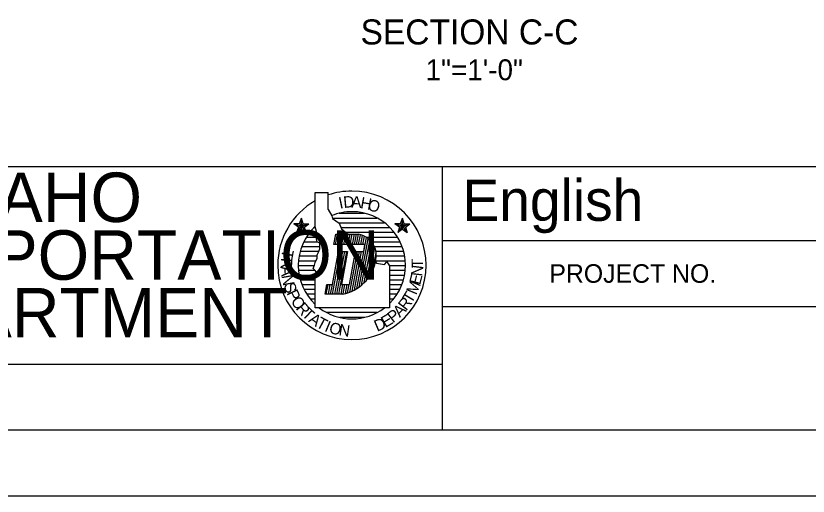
# Model space of a CAD drawing. Extents: x 0 to 34, y 0 to 23.5.
# Drawn here: x 16.02 to 22.02, y 0 to 3.64 of the extents above; entities that cross this region are included whole.
import ezdxf

# ---------------------------------------------------------------- set-up
doc = ezdxf.new("R2010")
doc.units = 0
for name, color, linetype in [('BORDER_ANNO_Cutsheet', 7, 'Continuous'), ('BRDG_ANNO_Anno-Sheet', 7, 'Continuous'), ('BRDG_ANNO_General-Notes', 7, 'Continuous')]:
    doc.layers.add(name, color=color, linetype=linetype)

msp = doc.modelspace()

# ---------------------------------------------------------------- linework, layer by layer
at = {"layer": 'BORDER_ANNO_Cutsheet'}
msp.add_lwpolyline([(0, 22), (34, 22), (34, 0), (0, 0)], close=True, dxfattribs=at)
at = {"layer": 'BRDG_ANNO_Anno-Sheet'}
for p, q in [((1.5, 2.5), (19.25, 2.5)), ((19.25, 0.5), (19.25, 2.5)), ((19.25, 2.5), (33.5, 2.5)), ((18.2844, 2.0425), (18.2844, 2.3031)), ((18.2844, 2.3031), (18.3831, 2.3031)), ((18.3831, 2.1731), (18.3831, 2.3031)), ((18.3831, 2.1731), (18.4094, 2.1262)), ((18.1656, 2.0656), (18.1794, 2.1069)), ((18.1794, 2.0237), (18.1794, 2.1069)), ((18.1931, 2.0656), (18.1794, 2.1069)), ((18.4094, 2.1262), (18.4144, 2.105)), ((18.4144, 2.105), (18.4662, 2.0688)), ((18.4169, 2.1081), (18.7506, 2.1081)), ((18.465, 2.1444), (18.6581, 2.1444)), ((18.9319, 2.0656), (18.9456, 2.1069)), ((18.9456, 2.0237), (18.9456, 2.1069)), ((18.9594, 2.0656), (18.9456, 2.1069)), ((18.2012, 2.04), (18.1225, 2.0656)), ((18.1656, 2.0656), (18.1225, 2.0656)), ((18.1575, 2.04), (18.1225, 2.0656)), ((18.1931, 2.0656), (18.1438, 1.9981)), ((18.1575, 2.04), (18.2369, 2.0656)), ((18.1656, 2.0656), (18.215, 1.9981)), ((18.1931, 2.0656), (18.2369, 2.0656)), ((18.2012, 2.04), (18.2369, 2.0656)), ((18.2944, 2.0063), (18.2844, 2.0425)), ((18.465, 2.0725), (18.8069, 2.0725)), ((18.4662, 2.0688), (18.4825, 2.0269)), ((18.9675, 2.04), (18.8881, 2.0656)), ((18.9237, 2.04), (18.8881, 2.0656)), ((18.9319, 2.0656), (18.8881, 2.0656)), ((18.9594, 2.0656), (18.91, 1.9981)), ((18.9237, 2.04), (19.0025, 2.0656)), ((18.9319, 2.0656), (18.9812, 1.9981)), ((18.9594, 2.0656), (19.0025, 2.0656)), ((18.9675, 2.04), (19.0025, 2.0656)), ((18.1575, 2.04), (18.1438, 1.9981)), ((18.1794, 2.0237), (18.1438, 1.9981)), ((18.1794, 2.0237), (18.215, 1.9981)), ((18.2012, 2.04), (18.215, 1.9981)), ((18.2419, 2.0006), (18.2937, 2.0006)), ((18.2744, 2.0362), (18.2862, 2.0362)), ((18.2944, 1.975), (18.2944, 2.0063)), ((18.425, 1.9069), (18.4406, 1.9856)), ((18.4394, 1.9069), (18.4537, 1.9856)), ((18.4406, 1.9856), (18.6125, 1.9856)), ((18.455, 1.9069), (18.47, 1.9856)), ((18.4712, 1.9069), (18.4856, 1.9856)), ((18.4787, 2.0362), (18.8506, 2.0362)), ((18.4825, 2.0269), (18.5344, 1.9856)), ((18.4869, 1.9069), (18.5019, 1.9856)), ((18.5025, 1.9069), (18.5175, 1.9856)), ((18.5156, 2.0006), (18.8825, 2.0006)), ((18.5188, 1.9069), (18.5331, 1.9856)), ((18.5344, 1.9069), (18.5494, 1.9856)), ((18.5506, 1.9069), (18.565, 1.9856)), ((18.5663, 1.9069), (18.5813, 1.9856)), ((18.5825, 1.9069), (18.5969, 1.9856)), ((18.5981, 1.9069), (18.6131, 1.9856)), ((18.9237, 2.04), (18.91, 1.9981)), ((18.9456, 2.0237), (18.91, 1.9981)), ((18.9456, 2.0237), (18.9812, 1.9981)), ((18.9675, 2.04), (18.9812, 1.9981)), ((18.1969, 1.9281), (18.2981, 1.9281)), ((18.2169, 1.9644), (18.2925, 1.9644)), ((18.2944, 1.9487), (18.2944, 1.975)), ((18.3, 1.9281), (18.2944, 1.9487)), ((18.3206, 1.9175), (18.3, 1.9281)), ((18.5994, 1.5744), (18.6719, 1.9619)), ((18.6137, 1.9069), (18.6281, 1.9812)), ((18.6175, 1.5856), (18.6863, 1.9519)), ((18.63, 1.9069), (18.6431, 1.9769)), ((18.6363, 1.6006), (18.6994, 1.9387)), ((18.6456, 1.9069), (18.6575, 1.97)), ((18.6556, 1.6187), (18.7125, 1.9244)), ((18.6687, 1.9644), (18.9075, 1.9644)), ((18.71, 1.9281), (18.9275, 1.9281)), ((19.25, 1.9375), (22.25, 1.9375)), ((18.1812, 1.8925), (18.3187, 1.8925)), ((18.31, 1.85), (18.3206, 1.8756)), ((18.3206, 1.8912), (18.3206, 1.9175)), ((18.3206, 1.8756), (18.3206, 1.8912)), ((18.6612, 1.9069), (18.425, 1.9069)), ((18.6519, 1.855), (18.6612, 1.9069)), ((18.6756, 1.64), (18.725, 1.9062)), ((18.6969, 1.6687), (18.7369, 1.8819)), ((18.7325, 1.8925), (18.9431, 1.8925)), ((18.1625, 1.8206), (18.2981, 1.8206)), ((18.1706, 1.8562), (18.3113, 1.8562)), ((18.2844, 1.7719), (18.3, 1.8031)), ((18.3, 1.8287), (18.31, 1.85)), ((18.3, 1.8031), (18.3, 1.8287)), ((18.4144, 1.605), (18.4612, 1.855)), ((18.4162, 1.5319), (18.4769, 1.855)), ((18.4325, 1.5319), (18.4931, 1.855)), ((18.4481, 1.5319), (18.5087, 1.855)), ((18.4612, 1.855), (18.53, 1.855)), ((18.4644, 1.5319), (18.525, 1.855)), ((18.53, 1.855), (18.4831, 1.605)), ((18.5437, 1.605), (18.5906, 1.855)), ((18.5469, 1.5475), (18.6044, 1.855)), ((18.5637, 1.555), (18.62, 1.855)), ((18.5813, 1.5631), (18.6363, 1.855)), ((18.5906, 1.855), (18.6519, 1.855)), ((18.7219, 1.7175), (18.7456, 1.845)), ((18.7444, 1.8562), (18.9544, 1.8562)), ((18.7475, 1.8206), (18.9625, 1.8206)), ((18.1562, 1.7481), (18.2775, 1.7481)), ((18.1575, 1.7844), (18.2906, 1.7844)), ((18.2688, 1.725), (18.2787, 1.7506)), ((18.2787, 1.7506), (18.2844, 1.7719)), ((18.7406, 1.7775), (18.7481, 1.7662)), ((18.7425, 1.7844), (18.9675, 1.7844)), ((18.7481, 1.7662), (18.7794, 1.7612)), ((18.7794, 1.7612), (18.8106, 1.7562)), ((18.8106, 1.7562), (18.8262, 1.7769)), ((18.8262, 1.7769), (18.8469, 1.7456)), ((18.845, 1.7481), (18.9688, 1.7481)), ((18.8469, 1.7456), (18.8469, 1.4275)), ((18.1581, 1.7125), (18.2812, 1.7125)), ((18.2844, 1.7094), (18.2688, 1.725)), ((18.2944, 1.6937), (18.2844, 1.7094)), ((18.3, 1.6831), (18.2944, 1.6937)), ((18.3, 1.6675), (18.3, 1.6831)), ((18.8475, 1.7125), (18.9669, 1.7125)), ((18.1631, 1.6763), (18.2981, 1.6763)), ((18.1713, 1.6406), (18.2837, 1.6406)), ((18.2844, 1.6519), (18.3, 1.6675)), ((18.2844, 1.4275), (18.2844, 1.6519)), ((18.8469, 1.6763), (18.9619, 1.6763)), ((18.8469, 1.6406), (18.9537, 1.6406)), ((18.1837, 1.6044), (18.2825, 1.6044)), ((18.1994, 1.5681), (18.2825, 1.5681)), ((18.3594, 1.5319), (18.3731, 1.605)), ((18.3687, 1.5319), (18.3825, 1.605)), ((18.3731, 1.605), (18.4144, 1.605)), ((18.385, 1.5319), (18.3987, 1.605)), ((18.4006, 1.5319), (18.4144, 1.605)), ((18.48, 1.5319), (18.4937, 1.605)), ((18.4831, 1.605), (18.5437, 1.605)), ((18.4962, 1.5325), (18.51, 1.605)), ((18.5131, 1.5369), (18.5256, 1.605)), ((18.53, 1.5419), (18.5412, 1.605)), ((18.8469, 1.6044), (18.9413, 1.6044)), ((18.8469, 1.5681), (18.925, 1.5681)), ((18.22, 1.5325), (18.2831, 1.5325)), ((18.4925, 1.5319), (18.3594, 1.5319)), ((18.8469, 1.5325), (18.905, 1.5325)), ((18.2456, 1.4962), (18.2825, 1.4962)), ((18.2775, 1.4606), (18.2837, 1.4606)), ((18.8469, 1.4962), (18.88, 1.4962)), ((18.8469, 1.4275), (18.2844, 1.4275)), ((18.7506, 1.3912), (18.3719, 1.3912)), ((19.25, 1.4375), (22.25, 1.4375)), ((18.6587, 1.3556), (18.4675, 1.3556)), ((14, 1), (19.25, 1))]:
    msp.add_line(p, q, dxfattribs=at)
msp.add_lwpolyline([(1.5, 21.5), (33.5, 21.5), (33.5, 0.5), (1.5, 0.5)], close=True, dxfattribs=at)
for centre, radius, start, end in [((18.5625, 1.75), 0.5625, 90, 108.596), ((18.5625, 1.75), 0.5625, 0, 90), ((18.5625, 1.75), 0.5625, 119.63312, 180), ((18.5625, 1.75), 0.4063, 90, 112.14518), ((18.5625, 1.75), 0.4063, 0, 90), ((18.5625, 1.75), 0.4063, 133.19257, 180), ((18.5833, 1.8241), 0.1641, 343.49805, 79.73615), ((18.5625, 1.75), 0.5625, 180, 270), ((18.5625, 1.75), 0.4063, 180.26444, 226.79463), ((18.4349, 1.8382), 0.3117, 280.64795, 348.77185), ((18.5625, 1.75), 0.5625, 270, 0), ((18.5625, 1.75), 0.4063, 314.427, 0), ((18.5625, 1.75), 0.4063, 232.5658, 270), ((18.5625, 1.75), 0.4063, 270, 307.45359)]:
    msp.add_arc(centre, radius, start, end, dxfattribs=at)

# ---------------------------------------------------------------- texts
for s, height, p in [('IDAHO', 0.375, (15.3837, 2.0781)), ('English', 0.3125, (19.4006, 2.0869)), ('TRANSPORTATION', 0.375, (14.1469, 1.6406)), ('PROJECT NO.', 0.140625, (20.0591, 1.6175)), ('DEPARTMENT', 0.375, (14.6194, 1.2031))]:
    msp.add_text(s, height=height, dxfattribs=at).set_placement(p)
for s, rotation, p in [('I', 11.95188, (18.4719, 2.1781)), ('D', 5.21184, (18.5012, 2.1844)), ('A', 357.8718, (18.5569, 2.1881)), ('H', 349.63177, (18.6219, 2.1837)), ('O', 342.19173, (18.6744, 2.1731)), ('T', 259.42648, (18.0381, 1.8756)), ('R', 266.0275, (18.0263, 1.8075)), ('N', 83.19321, (19.095, 1.6631)), ('T', 90.49256, (19.1019, 1.7294)), ('A', 273.76404, (18.0231, 1.7406)), ('E', 75.61046, (19.0794, 1.5969)), ('N', 280.37584, (18.0287, 1.6712)), ('M', 67.71394, (19.0506, 1.5206)), ('S', 287.92792, (18.0431, 1.6038)), ('P', 295.49755, (18.0656, 1.5406)), ('O', 302.64464, (18.0956, 1.48)), ('R', 52.33438, (18.9737, 1.4012)), ('T', 59.03624, (19.0137, 1.455)), ('R', 309.90789, (18.1337, 1.4225)), ('A', 45, (18.9256, 1.3506)), ('T', 317.1211, (18.1775, 1.3712)), ('E', 30.54757, (18.8156, 1.2737)), ('P', 37.66562, (18.8731, 1.3094)), ('A', 324.63754, (18.2281, 1.3256)), ('T', 331.75026, (18.2844, 1.2869)), ('I', 337.0213, (18.3494, 1.2537)), ('D', 22.98872, (18.7531, 1.2456)), ('O', 343.32869, (18.3825, 1.2406)), ('N', 351.65981, (18.4587, 1.22))]:
    msp.add_text(s, height=0.0869, rotation=rotation, dxfattribs=at).set_placement(p)
at = {"layer": 'BRDG_ANNO_General-Notes'}
for s, height, p in [('SECTION C-C', 0.19, (18.6281, 3.424)), ('1"=1\'-0"', 0.15833, (19.1205, 3.1531))]:
    msp.add_text(s, height=height, dxfattribs=at).set_placement(p)

doc.saveas('drawing.dxf')
